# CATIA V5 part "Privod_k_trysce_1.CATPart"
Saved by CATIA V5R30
Part number: Privod_k_trysce_1
Definition: EH 4100/37x60/11
Nomenclature: EH 4100/37x60/11
Source: Unknown
Description: PART--DESC
Bounding box of the stored display mesh (mm): x 71.75 to 108.25, y -18.246 to 18.246, z -24.6 to 55.7
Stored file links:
  E:\Bakalarka\Model\Forma_v7\Privod_k_trysce_1.CATPart
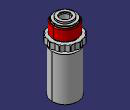
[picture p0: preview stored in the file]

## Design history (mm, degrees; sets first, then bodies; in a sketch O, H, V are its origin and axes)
Body1 "MANIFOLD_SOLID_BREP #3578" (main body)
  Solid1: solid without history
